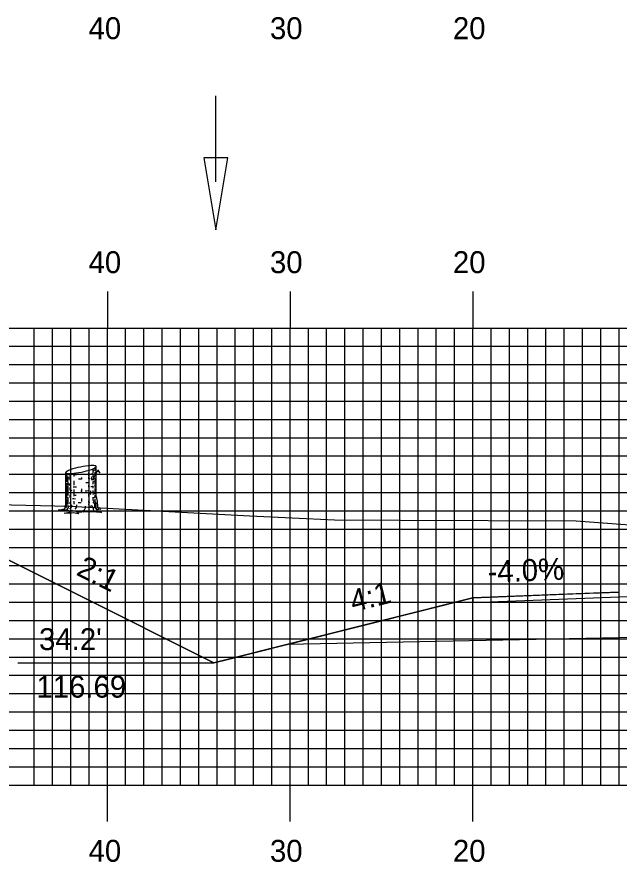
# Model space of a CAD drawing. Extents: x 1770842 to 1771185, y 442591 to 442811.
# Drawn here: x 1770962.61 to 1770995.55, y 442709.45 to 442755.68 of the extents above; entities that cross this region are included whole.
import ezdxf

# ---------------------------------------------------------------- set-up
doc = ezdxf.new("R2010")
doc.units = 0
for name, color, linetype in [('ANNOTATION', 7, 'Continuous'), ('D_Drainage_Ditch_Line', 7, 'Continuous'), ('D_Roadway_Centerline', 7, 'Continuous'), ('D_Roadway_Edge_Shoulder', 7, 'Continuous'), ('D_Roadway_SlopeLines', 7, 'Continuous'), ('D_Roadway_SubGrade', 7, 'Continuous'), ('H_V ANNOTATION', 7, 'Continuous'), ('M_Trees_Conifer_Pay', 7, 'Continuous'), ('MAJOR', 7, 'Continuous'), ('MINOR', 7, 'Continuous'), ('PDRAIN', 7, 'Continuous'), ('S_Roadway_Centerline', 7, 'Continuous')]:
    doc.layers.add(name, color=color, linetype=linetype)

msp = doc.modelspace()

# ---------------------------------------------------------------- linework, layer by layer
at = {"layer": 'D_Drainage_Ditch_Line'}
msp.add_line((1770973.492, 442746.659), (1770973.492, 442751.358), dxfattribs=at)
msp.add_lwpolyline([(1770974.149, 442747.972), (1770972.836, 442747.972), (1770973.492, 442744.035)], close=True, dxfattribs=at)
at = {"layer": 'D_Roadway_Centerline'}
msp.add_lwpolyline([(1770953.331, 442729.163), (1770954.581, 442729.069), (1770955.831, 442728.823), (1770957.081, 442728.426), (1770958.172, 442727.947), (1770958.331, 442727.877), (1770973.38, 442720.352), (1770974.203, 442720.558), (1770977.381, 442721.352), (1770977.384, 442721.353), (1770981.816, 442722.461), (1770987.554, 442723.896), (1770993.939, 442724.152), (1770995.554, 442724.216)], dxfattribs=at)
at = {"layer": 'D_Roadway_Edge_Shoulder'}
msp.add_lwpolyline([(1770995.554, 442724.216), (1770987.554, 442723.896), (1770987.554, 442723.646), (1770995.554, 442723.966)], close=True, dxfattribs=at)
at = {"layer": 'D_Roadway_SlopeLines'}
for points in [[(1770973.38, 442720.352), (1770958.33, 442727.877), (1770957.081, 442728.426), (1770955.831, 442728.823), (1770954.581, 442729.069), (1770953.331, 442729.163)], [(1770987.554, 442723.896), (1770973.38, 442720.352)]]:
    msp.add_lwpolyline(points, dxfattribs=at)
at = {"layer": 'D_Roadway_SubGrade'}
msp.add_lwpolyline([(1770995.554, 442721.716), (1770977.381, 442721.352), (1770987.554, 442723.896), (1770987.554, 442723.646), (1770995.554, 442723.966), (1771007.555, 442724.206), (1771019.555, 442723.966), (1771027.554, 442723.646), (1771027.554, 442723.896), (1771037.729, 442721.352), (1771019.555, 442721.716), (1771007.555, 442721.956)], close=True, dxfattribs=at)
at = {"layer": 'M_Trees_Conifer_Pay'}
for p, q in [((1770966.753, 442730.955), (1770966.753, 442730.732)), ((1770966.87, 442731.016), (1770966.87, 442730.854)), ((1770966.87, 442730.786), (1770966.87, 442730.658)), ((1770966.942, 442729.442), (1770966.942, 442731.089)), ((1770965.278, 442729.031), (1770965.278, 442730.753)), ((1770965.325, 442730.716), (1770965.325, 442730.245)), ((1770965.384, 442730.705), (1770965.384, 442730.607)), ((1770965.384, 442730.533), (1770965.384, 442730.329)), ((1770965.509, 442730.697), (1770965.509, 442730.465)), ((1770965.509, 442730.424), (1770965.509, 442730.35)), ((1770965.729, 442730.717), (1770965.729, 442730.549)), ((1770966.134, 442730.486), (1770966.134, 442730.39)), ((1770966.525, 442730.759), (1770966.525, 442730.56)), ((1770966.525, 442730.502), (1770966.525, 442730.413)), ((1770966.753, 442730.644), (1770966.753, 442730.596)), ((1770966.81, 442730.461), (1770966.759, 442730.401)), ((1770966.87, 442730.471), (1770966.87, 442730.135)), ((1770965.325, 442730.18), (1770965.325, 442729.872)), ((1770965.384, 442730.271), (1770965.384, 442730.072)), ((1770965.384, 442730.024), (1770965.384, 442729.688)), ((1770965.509, 442729.946), (1770965.509, 442729.808)), ((1770965.729, 442730.312), (1770965.729, 442730.075)), ((1770966.134, 442729.872), (1770966.134, 442729.798)), ((1770966.525, 442730.066), (1770966.525, 442729.961)), ((1770966.753, 442730.261), (1770966.753, 442730.129)), ((1770966.753, 442730.018), (1770966.753, 442729.909)), ((1770966.87, 442730.098), (1770966.87, 442729.936)), ((1770966.87, 442729.888), (1770966.87, 442729.672)), ((1770965.325, 442729.825), (1770965.325, 442729.333)), ((1770965.384, 442729.635), (1770965.384, 442729.499)), ((1770965.384, 442729.4), (1770965.384, 442729.022)), ((1770965.509, 442729.536), (1770965.509, 442729.394)), ((1770965.729, 442729.831), (1770965.729, 442729.678)), ((1770965.729, 442729.635), (1770965.729, 442729.462)), ((1770966.134, 442729.773), (1770966.134, 442729.625)), ((1770966.525, 442729.594), (1770966.525, 442729.448)), ((1770966.753, 442729.773), (1770966.753, 442729.631)), ((1770966.753, 442729.404), (1770966.753, 442729.232)), ((1770966.87, 442729.641), (1770966.87, 442729.567)), ((1770966.87, 442729.526), (1770966.87, 442729.353)), ((1770965.325, 442729.279), (1770965.325, 442729.031)), ((1770965.509, 442729.133), (1770965.509, 442729.038)), ((1770965.729, 442729.184), (1770965.729, 442729.031)), ((1770966.134, 442729.333), (1770966.134, 442729.18)), ((1770966.525, 442729.215), (1770966.525, 442729.127)), ((1770965.509, 442728.638), (1770965.672, 442728.702)), ((1770965.946, 442728.574), (1770965.82, 442728.638))]:
    msp.add_line(p, q, dxfattribs=at)
for points in [[(1770966.759, 442730.587), (1770966.796, 442730.512), (1770966.843, 442730.57), (1770966.901, 442730.638), (1770966.993, 442730.831), (1770967.057, 442730.879), (1770967.088, 442730.885)], [(1770966.773, 442730.333), (1770966.81, 442730.461), (1770966.874, 442730.576), (1770966.905, 442730.644), (1770966.973, 442730.79)], [(1770966.988, 442730.82), (1770967.063, 442730.827), (1770967.136, 442730.728)], [(1770966.725, 442730.549), (1770966.695, 442730.465), (1770966.691, 442730.397), (1770966.721, 442730.333)], [(1770965.457, 442730.059), (1770965.451, 442730.154), (1770965.494, 442730.131), (1770965.494, 442730.037)], [(1770966.942, 442729.442), (1770966.993, 442729.18), (1770967.01, 442728.906), (1770967.067, 442728.781), (1770967.203, 442728.75), (1770966.973, 442728.713), (1770966.973, 442728.713), (1770966.979, 442728.665), (1770967.226, 442728.571), (1770966.952, 442728.587), (1770966.596, 442728.608), (1770966.275, 442728.597), (1770966.281, 442728.68), (1770966.133, 442728.597), (1770965.946, 442728.574), (1770965.97, 442728.507), (1770965.702, 442728.55), (1770965.482, 442728.523), (1770965.189, 442728.54), (1770965.478, 442728.597), (1770965.509, 442728.638), (1770965.346, 442728.696), (1770965.109, 442728.707), (1770964.868, 442728.707), (1770965.21, 442728.764), (1770965.252, 442728.844), (1770965.278, 442729.031)], [(1770966.596, 442729.66), (1770966.609, 442729.583), (1770966.656, 442729.594), (1770966.643, 442729.76)], [(1770965.326, 442728.984), (1770965.305, 442728.906), (1770965.284, 442728.812)], [(1770965.404, 442728.964), (1770965.41, 442728.848), (1770965.357, 442728.76), (1770965.346, 442728.696)], [(1770965.567, 442728.991), (1770965.567, 442728.859), (1770965.478, 442728.76)], [(1770965.793, 442728.75), (1770965.861, 442728.844), (1770965.888, 442728.984)], [(1770966.532, 442729.049), (1770966.542, 442728.923), (1770966.617, 442728.879)], [(1770966.769, 442729.154), (1770966.843, 442729.049), (1770966.847, 442728.875), (1770966.973, 442728.713)], [(1770966.868, 442729.299), (1770966.874, 442729.154), (1770966.921, 442729.085), (1770966.931, 442728.886)], [(1770966.281, 442728.68), (1770966.355, 442728.822), (1770966.365, 442728.923)], [(1770966.81, 442728.659), (1770966.796, 442728.797), (1770966.721, 442728.927)]]:
    msp.add_lwpolyline(points, dxfattribs=at)
for centre, radius, start, end in [((1770965.353, 442730.728), 0.0817, 132.3887, 146.7194), ((1770965.467, 442730.603), 0.251, 124.2194, 132.3887), ((1770965.777, 442730.147), 0.802, 108.0594, 124.2194), ((1770967.134, 442725.986), 5.179, 101.7194, 108.0594), ((1770965.086, 442735.856), 5.179, 275.3794, 281.7194), ((1770967.134, 442725.986), 5.179, 95.3794, 101.7194), ((1770965.086, 442735.856), 5.179, 281.7194, 288.0594), ((1770966.723, 442730.344), 0.802, 79.2194, 95.3794), ((1770966.443, 442731.694), 0.802, 288.0594, 304.2194), ((1770966.611, 442731.402), 0.571, 284.4317, 292.4132), ((1770966.827, 442730.885), 0.251, 71.0501, 79.2194), ((1770966.753, 442731.239), 0.251, 304.2194, 312.3887), ((1770966.81, 442731.057), 0.172, 300, 311.2506), ((1770966.881, 442731.045), 0.0817, 56.7194, 71.0501), ((1770966.867, 442731.114), 0.0817, 312.3887, 326.7194), ((1770966.883, 442730.974), 0.0624, 311.2506, 330), ((1770966.883, 442730.82), 0.0624, 311.2506, 330), ((1770966.897, 442731.069), 0.0527, 46.923, 56.7194), ((1770966.912, 442731.084), 0.0314, 34.2194, 46.923), ((1770966.891, 442731.098), 0.0527, 326.7194, 336.5158), ((1770966.899, 442730.965), 0.0441, 330, 343.9485), ((1770966.899, 442730.811), 0.0441, 330, 343.9485), ((1770966.916, 442731.087), 0.0264, 23.4074, 34.2194), ((1770966.919, 442731.089), 0.0226, 11.7194, 23.4074), ((1770966.911, 442731.09), 0.0314, 336.5158, 349.2194), ((1770966.909, 442730.962), 0.0334, 343.9485, 354.2151), ((1770966.909, 442730.808), 0.0334, 343.9485, 354.2151), ((1770966.919, 442731.089), 0.0226, 0.0315, 11.7194), ((1770966.916, 442731.089), 0.0264, 349.2194, 0.0315), ((1770965.31, 442730.575), 0.0334, 163.9485, 180), ((1770965.31, 442730.575), 0.0334, 180, 196.0515), ((1770965.304, 442730.753), 0.0264, 169.2194, 180.0315), ((1770965.301, 442730.753), 0.0226, 180.0315, 191.7194), ((1770965.32, 442730.578), 0.0441, 196.0515, 210), ((1770965.309, 442730.752), 0.0314, 156.5158, 169.2194), ((1770965.301, 442730.753), 0.0226, 191.7194, 203.4074), ((1770965.304, 442730.754), 0.0264, 203.4074, 214.2194), ((1770965.329, 442730.744), 0.0527, 146.7194, 156.5158), ((1770965.308, 442730.757), 0.0314, 214.2194, 226.923), ((1770965.336, 442730.587), 0.0624, 210, 228.7494), ((1770965.323, 442730.773), 0.0527, 226.923, 236.7194), ((1770965.339, 442730.797), 0.0817, 236.7194, 251.0501), ((1770965.409, 442730.67), 0.172, 228.7494, 240), ((1770965.394, 442730.957), 0.251, 251.0501, 259.2194), ((1770965.608, 442731.015), 0.571, 240, 240.3367), ((1770965.497, 442731.498), 0.802, 259.2194, 275.3794), ((1770965.608, 442731.015), 0.571, 246.8597, 257.9846), ((1770966.11, 442734.765), 4.124, 264.6955, 266.7331), ((1770966.109, 442734.532), 4.124, 268.0751, 270), ((1770966.109, 442734.532), 4.124, 270, 270.3581), ((1770966.109, 442734.532), 4.124, 275.7849, 277.0558), ((1770966.11, 442734.765), 4.124, 276.238, 278.1032), ((1770966.611, 442731.248), 0.571, 278.1032, 284.3667), ((1770966.611, 442731.248), 0.571, 297.0237, 300), ((1770966.81, 442730.903), 0.172, 300, 311.2506), ((1770966.909, 442730.364), 0.0334, 343.9485, 354.2151), ((1770965.31, 442730.128), 0.0334, 163.9485, 180), ((1770965.31, 442730.128), 0.0334, 180, 196.0515), ((1770965.31, 442729.918), 0.0334, 163.9485, 180), ((1770965.31, 442729.918), 0.0334, 180, 196.0515), ((1770965.32, 442730.131), 0.0441, 196.0515, 210), ((1770965.32, 442729.921), 0.0441, 196.0515, 210), ((1770965.336, 442730.14), 0.0624, 210, 228.7494), ((1770965.336, 442729.93), 0.0624, 210, 228.7494), ((1770965.409, 442730.223), 0.172, 228.7494, 240), ((1770965.409, 442730.013), 0.172, 228.7494, 240), ((1770965.608, 442730.568), 0.571, 240, 240.3367), ((1770965.608, 442730.358), 0.571, 240, 246.8597), ((1770965.609, 442730.804), 0.571, 240, 247.0587), ((1770966.109, 442734.086), 4.124, 264.081, 266.6676), ((1770966.11, 442734.321), 4.124, 273.7052, 275.9504), ((1770966.109, 442734.086), 4.124, 277.6125, 278.1032), ((1770966.61, 442730.568), 0.571, 278.1032, 286.9296), ((1770966.611, 442730.804), 0.571, 284.4493, 297.0429), ((1770966.61, 442730.568), 0.571, 297.1896, 300), ((1770966.61, 442730.358), 0.571, 297.1896, 300), ((1770966.809, 442730.223), 0.172, 300, 311.2506), ((1770966.809, 442730.013), 0.172, 300, 311.2506), ((1770966.881, 442730.14), 0.0624, 311.2506, 330), ((1770966.881, 442729.93), 0.0624, 311.2506, 330), ((1770966.897, 442730.131), 0.0441, 330, 343.9485), ((1770966.897, 442729.921), 0.0441, 330, 343.9485), ((1770966.907, 442730.128), 0.0334, 343.9485, 354.2151), ((1770966.907, 442729.918), 0.0334, 343.9485, 354.2151), ((1770965.31, 442729.681), 0.0334, 163.9485, 180), ((1770965.31, 442729.681), 0.0334, 180, 196.0515), ((1770965.31, 442729.484), 0.0334, 163.9485, 180), ((1770965.32, 442729.684), 0.0441, 196.0515, 210), ((1770965.336, 442729.694), 0.0624, 210, 228.7494), ((1770965.409, 442729.776), 0.172, 228.7494, 240), ((1770965.608, 442730.121), 0.571, 240, 246.8597), ((1770965.597, 442729.93), 0.571, 241.2369, 248.0268), ((1770965.608, 442730.358), 0.571, 259.2707, 261.8968), ((1770966.109, 442733.876), 4.124, 261.8968, 263.1474), ((1770966.109, 442733.639), 4.124, 264.716, 266.3193), ((1770966.109, 442733.876), 4.124, 270, 270.3581), ((1770966.109, 442733.876), 4.124, 273.1493, 275.4569), ((1770966.61, 442730.121), 0.571, 285.3983, 297.1896), ((1770966.61, 442729.924), 0.571, 289.2907, 300), ((1770966.809, 442729.578), 0.172, 300, 311.2506), ((1770966.881, 442729.496), 0.0624, 311.2506, 330), ((1770966.897, 442729.487), 0.0441, 330, 343.9485), ((1770966.907, 442729.484), 0.0334, 343.9485, 354.2151), ((1770965.31, 442729.288), 0.0334, 163.9485, 180), ((1770965.31, 442729.288), 0.0334, 180, 196.0515), ((1770965.31, 442729.068), 0.0334, 163.9485, 180), ((1770965.31, 442729.068), 0.0334, 180, 196.0515), ((1770965.32, 442729.291), 0.0441, 196.0515, 210), ((1770965.32, 442729.071), 0.0441, 196.0515, 210), ((1770965.336, 442729.3), 0.0624, 210, 228.7494), ((1770965.336, 442729.08), 0.0624, 210, 228.7494), ((1770965.409, 442729.383), 0.172, 228.7494, 240), ((1770965.409, 442729.163), 0.172, 228.7494, 240), ((1770965.608, 442729.728), 0.571, 240, 246.8597), ((1770965.608, 442729.508), 0.571, 240, 244.5314), ((1770966.109, 442733.025), 4.124, 262.4438, 263.512), ((1770966.109, 442733.441), 4.124, 263.4991, 265.8397), ((1770966.109, 442733.245), 4.124, 267.8117, 270), ((1770966.109, 442733.245), 4.124, 270, 270.1328), ((1770966.109, 442733.245), 4.124, 275.7849, 276.7896), ((1770966.109, 442733.025), 4.124, 277.3684, 278.1032), ((1770966.61, 442729.508), 0.571, 278.1032, 281.637), ((1770966.61, 442729.728), 0.571, 288.5067, 297.2721), ((1770966.809, 442729.163), 0.172, 300, 311.2506), ((1770966.881, 442729.08), 0.0624, 311.2506, 330), ((1770966.897, 442729.071), 0.0441, 330, 343.9485), ((1770966.907, 442729.068), 0.0334, 343.9485, 354.2151)]:
    msp.add_arc(centre, radius, start, end, dxfattribs=at)
at = {"layer": 'MAJOR'}
for p, q in [((1770967.554, 442740.669), (1770967.554, 442738.665)), ((1770977.554, 442740.669), (1770977.554, 442738.665)), ((1770987.554, 442740.669), (1770987.554, 442738.665)), ((1770867.554, 442738.665), (1771147.554, 442738.665)), ((1770867.554, 442738.665), (1771147.554, 442738.665)), ((1770967.554, 442713.665), (1770967.554, 442738.665)), ((1770977.554, 442713.665), (1770977.554, 442738.665)), ((1770987.554, 442713.665), (1770987.554, 442738.665)), ((1770867.554, 442733.665), (1771147.554, 442733.665)), ((1770867.554, 442728.665), (1771147.554, 442728.665)), ((1770867.554, 442723.665), (1771147.554, 442723.665)), ((1770867.554, 442718.665), (1771147.554, 442718.665)), ((1770867.554, 442713.665), (1771147.554, 442713.665)), ((1770867.554, 442713.665), (1771147.554, 442713.665)), ((1770967.554, 442711.661), (1770967.554, 442713.665)), ((1770977.554, 442711.661), (1770977.554, 442713.665)), ((1770987.554, 442711.661), (1770987.554, 442713.665))]:
    msp.add_line(p, q, dxfattribs=at)
at = {"layer": 'MINOR'}
for p, q in [((1770963.554, 442713.665), (1770963.554, 442738.665)), ((1770964.554, 442713.665), (1770964.554, 442738.665)), ((1770965.554, 442713.665), (1770965.554, 442738.665)), ((1770966.554, 442713.665), (1770966.554, 442738.665)), ((1770968.554, 442713.665), (1770968.554, 442738.665)), ((1770969.554, 442713.665), (1770969.554, 442738.665)), ((1770970.554, 442713.665), (1770970.554, 442738.665)), ((1770971.554, 442713.665), (1770971.554, 442738.665)), ((1770972.554, 442713.665), (1770972.554, 442738.665)), ((1770973.554, 442713.665), (1770973.554, 442738.665)), ((1770974.554, 442713.665), (1770974.554, 442738.665)), ((1770975.554, 442713.665), (1770975.554, 442738.665)), ((1770976.554, 442713.665), (1770976.554, 442738.665)), ((1770978.554, 442713.665), (1770978.554, 442738.665)), ((1770979.554, 442713.665), (1770979.554, 442738.665)), ((1770980.554, 442713.665), (1770980.554, 442738.665)), ((1770981.554, 442713.665), (1770981.554, 442738.665)), ((1770982.554, 442713.665), (1770982.554, 442738.665)), ((1770983.554, 442713.665), (1770983.554, 442738.665)), ((1770984.554, 442713.665), (1770984.554, 442738.665)), ((1770985.554, 442713.665), (1770985.554, 442738.665)), ((1770986.554, 442713.665), (1770986.554, 442738.665)), ((1770988.554, 442713.665), (1770988.554, 442738.665)), ((1770989.554, 442713.665), (1770989.554, 442738.665)), ((1770990.554, 442713.665), (1770990.554, 442738.665)), ((1770991.554, 442713.665), (1770991.554, 442738.665)), ((1770992.554, 442713.665), (1770992.554, 442738.665)), ((1770993.554, 442713.665), (1770993.554, 442738.665)), ((1770994.554, 442713.665), (1770994.554, 442738.665)), ((1770995.554, 442713.665), (1770995.554, 442738.665)), ((1770867.554, 442737.665), (1771147.554, 442737.665)), ((1770867.554, 442736.665), (1771147.554, 442736.665)), ((1770867.554, 442735.665), (1771147.554, 442735.665)), ((1770867.554, 442734.665), (1771147.554, 442734.665)), ((1770867.554, 442732.665), (1771147.554, 442732.665)), ((1770867.554, 442731.665), (1771147.554, 442731.665)), ((1770867.554, 442730.665), (1771147.554, 442730.665)), ((1770867.554, 442729.665), (1771147.554, 442729.665)), ((1770867.554, 442727.665), (1771147.554, 442727.665)), ((1770867.554, 442726.665), (1771147.554, 442726.665)), ((1770867.554, 442725.665), (1771147.554, 442725.665)), ((1770867.554, 442724.665), (1771147.554, 442724.665)), ((1770867.554, 442722.665), (1771147.554, 442722.665)), ((1770867.554, 442721.665), (1771147.554, 442721.665)), ((1770867.554, 442720.665), (1771147.554, 442720.665)), ((1770867.554, 442719.665), (1771147.554, 442719.665)), ((1770867.554, 442717.665), (1771147.554, 442717.665)), ((1770867.554, 442716.665), (1771147.554, 442716.665)), ((1770867.554, 442715.665), (1771147.554, 442715.665)), ((1770867.554, 442714.665), (1771147.554, 442714.665))]:
    msp.add_line(p, q, dxfattribs=at)
at = {"layer": 'PDRAIN'}
msp.add_line((1770962.657, 442720.352), (1770973.38, 442720.352), dxfattribs=at)
at = {"layer": 'S_Roadway_Centerline'}
msp.add_lwpolyline([(1770933.687, 442729.93), (1770944.441, 442729.295), (1770945.315, 442729.29), (1770946.696, 442729.261), (1770958.316, 442729.09), (1770965.485, 442728.914), (1770975.351, 442728.383), (1770979.985, 442728.177), (1770983.601, 442728.145), (1770993.203, 442728.125), (1771004.671, 442727.266), (1771004.696, 442727.264), (1771004.714, 442727.262), (1771017.09, 442726.642), (1771034.823, 442725.929), (1771040.183, 442725.841), (1771044.388, 442725.857), (1771052.299, 442725.802), (1771064.281, 442725.295), (1771064.347, 442725.294), (1771083.715, 442724.922)], dxfattribs=at)

# ---------------------------------------------------------------- texts
at = {"layer": 'ANNOTATION'}
for s, rotation, p in [('2:1', 333.4342, (1770965.789, 442725.184)), ('-4.0%', 2.2906, (1770988.378, 442724.731)), ('4:1', 14.0393, (1770981.005, 442723.12))]:
    msp.add_text(s, height=1.2, rotation=rotation, dxfattribs=at).set_placement(p)
for s, p in [("34.2'", (1770963.818, 442721.044)), ('116.69', (1770963.674, 442718.444))]:
    msp.add_text(s, height=1.2, dxfattribs=at).set_placement(p)
at = {"layer": 'H_V ANNOTATION'}
for s, p in [('40', (1770966.527, 442754.465)), ('30', (1770976.452, 442754.465)), ('20', (1770986.462, 442754.465)), ('40', (1770966.527, 442741.665)), ('30', (1770976.452, 442741.665)), ('20', (1770986.462, 442741.665)), ('40', (1770966.527, 442709.465)), ('30', (1770976.452, 442709.465)), ('20', (1770986.462, 442709.465))]:
    msp.add_text(s, height=1.2, dxfattribs=at).set_placement(p)

doc.saveas('drawing.dxf')
